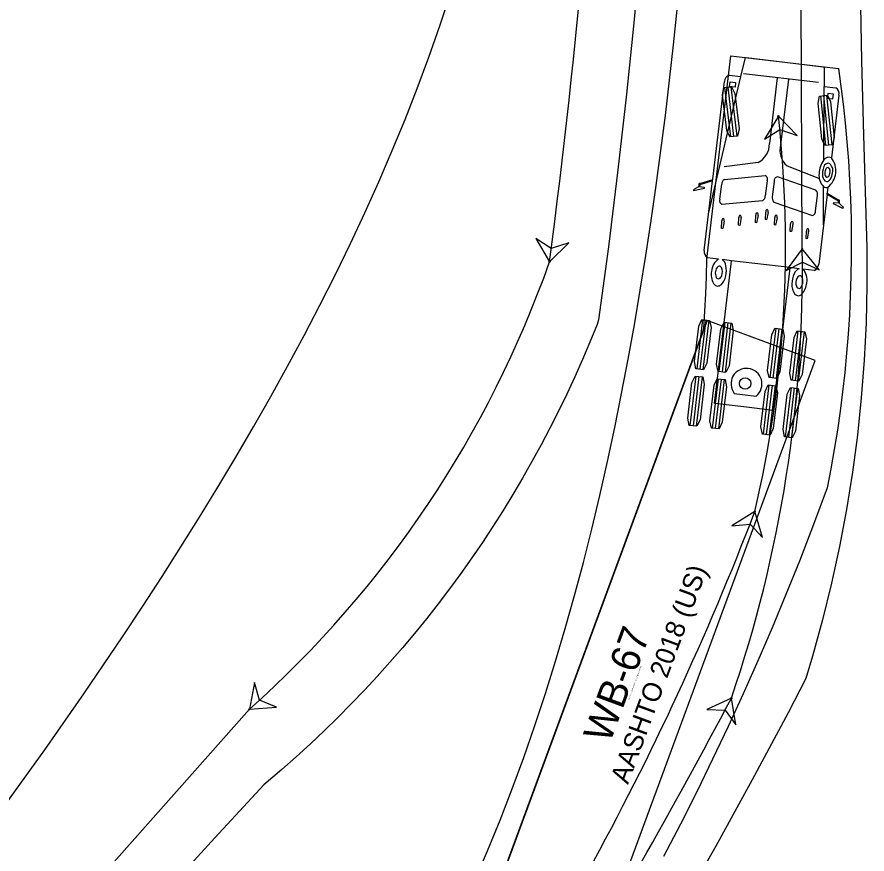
# Model space of a CAD drawing. Extents: x 973688 to 979179, y 703586 to 707602.
# Drawn here: x 976668.5 to 976731.2, y 705666.2 to 705727.9 of the extents above; entities that cross this region are included whole.
import ezdxf

# ---------------------------------------------------------------- set-up
doc = ezdxf.new("R2010")
doc.units = 0
doc.layers.add('EB Left', color=7, linetype='Continuous')
doc.layers.add('SB Right', color=7, linetype='Continuous')

msp = doc.modelspace()

# ---------------------------------------------------------------- linework, layer by layer
at = {"layer": 'EB Left'}
msp.add_line((976726.438, 705710.847), (976726.065, 705823.129), dxfattribs=at)
for points in [[(976702.259, 705664.192), (976703.224, 705666.439), (976704.151, 705668.711), (976705.041, 705671.008), (976705.895, 705673.329), (976706.714, 705675.674), (976707.497, 705678.04), (976708.247, 705680.428), (976708.963, 705682.837), (976709.647, 705685.264), (976710.299, 705687.71), (976710.92, 705690.173), (976711.511, 705692.651), (976712.074, 705695.145), (976712.609, 705697.652), (976713.118, 705700.172), (976713.6, 705702.704), (976714.058, 705705.246), (976714.492, 705707.799), (976714.904, 705710.361), (976715.294, 705712.931), (976715.663, 705715.51), (976716.343, 705720.687), (976716.95, 705725.889), (976717.493, 705731.11)], [(976730.706, 705730.152), (976730.816, 705724.697), (976730.954, 705719.214), (976731.211, 705710.924), (976731.221, 705708.153), (976731.156, 705705.384), (976731.016, 705702.619), (976730.8, 705699.858), (976730.509, 705697.104), (976730.144, 705694.357), (976729.704, 705691.62), (976729.188, 705688.894), (976728.599, 705686.181), (976727.935, 705683.484), (976727.198, 705680.805), (976726.699, 705679.141), (976725.396, 705676.628), (976722.75, 705671.666), (976720.066, 705666.787), (976717.348, 705661.995)], [(976726.438, 705710.847), (976725.249, 705709.239), (976726.456, 705709.847), (976727.683, 705709.282), (976726.438, 705710.847)], [(976721.216, 705677.7), (976719.398, 705676.865), (976720.749, 705676.815), (976721.552, 705675.728), (976721.216, 705677.7)]]:
    msp.add_lwpolyline(points, dxfattribs=at)
for points in [[(976726.438, 705710.847), (976725.249, 705709.239), (976726.456, 705709.847), (976727.683, 705709.282)], [(976721.216, 705677.7), (976719.398, 705676.865), (976720.749, 705676.815), (976721.552, 705675.728)]]:
    msp.add_lwpolyline(points, close=True, dxfattribs=at)
for centre in [(976726.438, 705710.847), (976721.216, 705677.7)]:
    msp.add_circle(centre, 0.0417, dxfattribs=at)
for centre, radius, start, end in [((976629.35, 705709.159), 97.103, 341.09639, 0.99621), ((976347.09, 705875.165), 423.04, 324.68102, 332.17475)]:
    msp.add_arc(centre, radius, start, end, dxfattribs=at)
at = {"layer": 'SB Right'}
for p, q in [((976727.632, 705723.1), (976722.108, 705723.759)), ((976719.566, 705713.629), (976721.919, 705723.555)), ((976721.074, 705722.814), (976721.117, 705723.167)), ((976721.117, 705723.167), (976721.526, 705723.118)), ((976721.526, 705723.118), (976721.484, 705722.765)), ((976724.6, 705723.462), (976724.02, 705718.605)), ((976725.428, 705723.363), (976724.848, 705718.506)), ((976720.72, 705722.737), (976721.156, 705719.096)), ((976720.947, 705722.764), (976721.384, 705719.124)), ((976721.484, 705722.765), (976721.074, 705722.814)), ((976721.175, 705722.792), (976721.611, 705719.151)), ((976728.029, 705717.395), (976728.055, 705722.822)), ((976727.783, 705722.115), (976728.16, 705718.468)), ((976728.011, 705722.139), (976728.388, 705718.491)), ((976728.239, 705722.162), (976728.616, 705718.515)), ((976728.334, 705722.306), (976728.292, 705721.953)), ((976728.292, 705721.953), (976728.702, 705721.904)), ((976728.744, 705722.257), (976728.334, 705722.306)), ((976728.702, 705721.904), (976728.744, 705722.257)), ((976723.197, 705717.213), (976720.672, 705716.877)), ((976725.321, 705716.959), (976727.708, 705716.034)), ((976720.707, 705715.962), (976723.699, 705716.255)), ((976719.833, 705715.863), (976719.845, 705715.962)), ((976720.366, 705714.492), (976720.5, 705715.614)), ((976723.852, 705715.863), (976723.718, 705714.741)), ((976724.367, 705715.802), (976724.233, 705714.679)), ((976727.446, 705715.158), (976724.607, 705716.146)), ((976718.84, 705715.455), (976718.816, 705715.441)), ((976718.868, 705715.45), (976718.84, 705715.455)), ((976728.006, 705712.622), (976728.02, 705715.428)), ((976728.273, 705714.856), (976728.285, 705714.955)), ((976723.51, 705714.393), (976720.518, 705714.1)), ((976724.353, 705714.292), (976727.192, 705713.304)), ((976727.432, 705713.648), (976727.566, 705714.771)), ((976729.113, 705714.228), (976729.141, 705714.226)), ((976729.141, 705714.226), (976729.162, 705714.206)), ((976721.739, 705712.584), (976721.767, 705713.16)), ((976721.934, 705713.14), (976721.828, 705712.574)), ((976722.987, 705712.772), (976723.014, 705713.322)), ((976723.181, 705713.302), (976723.077, 705712.761)), ((976723.725, 705712.995), (976723.752, 705713.545)), ((976723.919, 705713.525), (976723.815, 705712.984)), ((976724.39, 705712.605), (976724.416, 705713.155)), ((976724.583, 705713.135), (976724.479, 705712.594)), ((976720.484, 705712.346), (976720.51, 705712.896)), ((976720.678, 705712.876), (976720.573, 705712.335)), ((976721.828, 705712.574), (976721.739, 705712.584)), ((976723.077, 705712.761), (976722.987, 705712.772)), ((976723.815, 705712.984), (976723.725, 705712.995)), ((976724.479, 705712.594), (976724.39, 705712.605)), ((976725.559, 705712.128), (976725.586, 705712.679)), ((976725.753, 705712.659), (976725.649, 705712.118)), ((976720.573, 705712.335), (976720.484, 705712.346)), ((976725.649, 705712.118), (976725.559, 705712.128)), ((976726.723, 705711.601), (976726.749, 705712.151)), ((976726.916, 705712.132), (976726.812, 705711.59)), ((976726.812, 705711.59), (976726.723, 705711.601)), ((976725.529, 705709.454), (976721.229, 705709.967)), ((976719.093, 705705.623), (976718.659, 705701.982)), ((976719.321, 705705.596), (976718.886, 705701.955)), ((976719.548, 705705.569), (976719.114, 705701.928)), ((976720.732, 705705.428), (976720.297, 705701.787)), ((976720.959, 705705.4), (976720.525, 705701.76)), ((976721.187, 705705.373), (976720.752, 705701.732)), ((976724.488, 705704.979), (976724.054, 705701.338)), ((976724.716, 705704.952), (976724.281, 705701.311)), ((976724.943, 705704.925), (976724.509, 705701.284)), ((976726.127, 705704.784), (976725.692, 705701.143)), ((976726.354, 705704.757), (976725.92, 705701.116)), ((976726.582, 705704.729), (976726.147, 705701.089)), ((976718.596, 705701.453), (976718.161, 705697.812)), ((976718.823, 705701.426), (976718.389, 705697.785)), ((976719.051, 705701.398), (976718.616, 705697.758)), ((976720.234, 705701.257), (976719.8, 705697.616)), ((976720.462, 705701.23), (976720.027, 705697.589)), ((976720.689, 705701.203), (976720.255, 705697.562)), ((976723.991, 705700.809), (976723.556, 705697.168)), ((976724.218, 705700.782), (976723.784, 705697.141)), ((976724.446, 705700.755), (976724.011, 705697.114)), ((976725.629, 705700.613), (976725.195, 705696.972)), ((976725.857, 705700.586), (976725.422, 705696.945)), ((976726.084, 705700.559), (976725.65, 705696.918)), ((976721.432, 705700.176), (976723.037, 705699.984)), ((976685.668, 705676.879), (976635.767, 705620.712))]:
    msp.add_line(p, q, dxfattribs=at)
for points in [[(976714.521, 705733.032), (976714.039, 705727.751), (976713.479, 705722.257), (976712.849, 705716.671), (976712.145, 705710.995), (976711.417, 705705.6), (976711.306, 705705.266), (976710.779, 705703.966), (976710.23, 705702.675), (976709.661, 705701.394), (976709.07, 705700.124), (976708.459, 705698.863), (976707.828, 705697.613), (976707.176, 705696.375), (976706.504, 705695.148), (976705.813, 705693.932), (976705.101, 705692.729), (976704.371, 705691.538), (976703.621, 705690.359), (976702.851, 705689.193), (976702.063, 705688.04), (976701.256, 705686.901), (976700.43, 705685.774), (976699.586, 705684.662), (976698.724, 705683.563), (976697.843, 705682.478), (976696.944, 705681.408), (976696.028, 705680.351), (976695.093, 705679.31), (976694.14, 705678.283), (976693.17, 705677.271), (976692.182, 705676.273), (976691.176, 705675.292), (976690.153, 705674.325), (976689.112, 705673.374), (976688.053, 705672.439), (976686.731, 705671.31), (976683.104, 705667.39), (976681.323, 705665.437)], [(976667.634, 705669.825), (976670.553, 705673.881), (976673.451, 705678.03), (976676.347, 705682.299), (976677.789, 705684.477), (976679.21, 705686.663), (976680.609, 705688.856), (976681.986, 705691.058), (976683.339, 705693.268), (976684.665, 705695.486), (976685.965, 705697.712), (976687.237, 705699.945), (976688.478, 705702.187), (976689.688, 705704.437), (976690.864, 705706.694), (976692.006, 705708.958), (976693.112, 705711.23), (976694.18, 705713.508), (976695.208, 705715.792), (976696.196, 705718.082), (976697.14, 705720.377), (976698.041, 705722.677), (976698.896, 705724.982), (976699.705, 705727.29), (976700.467, 705729.602)], [(976704.605, 705665.378), (976719.091, 705704.657), (976719.179, 705704.962), (976719.266, 705706.237), (976719.333, 705707.514), (976719.379, 705708.791), (976719.405, 705710.07), (976721.184, 705725.079), (976729.128, 705724.131), (976729.467, 705721.518), (976729.617, 705720.125), (976729.745, 705718.727), (976729.852, 705717.322), (976729.938, 705715.912), (976730.002, 705714.496), (976730.044, 705713.073), (976730.064, 705711.67), (976730.061, 705710.248), (976730.037, 705708.825), (976729.99, 705707.4), (976729.921, 705705.977), (976729.83, 705704.555), (976729.716, 705703.134), (976729.58, 705701.715), (976729.422, 705700.297), (976729.241, 705698.879), (976729.037, 705697.462), (976728.811, 705696.044), (976728.561, 705694.626), (976728.278, 705693.211), (976727.273, 705690.506), (976726.233, 705687.816), (976725.243, 705685.35), (976724.223, 705682.895), (976723.171, 705680.452), (976722.089, 705678.02), (976720.976, 705675.6), (976719.832, 705673.191), (976718.658, 705670.793), (976717.451, 705668.407), (976716.214, 705666.033)], [(976721.06, 705723.657), (976721.911, 705723.556), (976721.92, 705723.557), (976722.25, 705724.951), (976722.313, 705724.944), (976725.156, 705724.605), (976727.999, 705724.266), (976728.062, 705724.258), (976728.055, 705722.824), (976728.064, 705722.821), (976728.914, 705722.72)], [(976718.887, 705715.655), (976719.835, 705715.959), (976719.846, 705715.97), (976720.705, 705723.176)], [(976729.146, 705722.168), (976728.595, 705717.557)], [(976724.682, 705720.633), (976723.648, 705718.921), (976724.793, 705719.639), (976726.068, 705719.191), (976724.682, 705720.633)], [(976719.219, 705710.723), (976719.833, 705715.863), (976718.895, 705715.567), (976718.895, 705715.567), (976718.879, 705715.532), (976718.878, 705715.531), (976718.878, 705715.53), (976718.868, 705715.451), (976718.869, 705715.45), (976719.213, 705715.393), (976719.201, 705715.291), (976718.456, 705715.121), (976718.454, 705715.121), (976718.468, 705715.239), (976718.471, 705715.241), (976718.814, 705715.44), (976718.816, 705715.442), (976718.827, 705715.528)], [(976728.336, 705715.386), (976728.286, 705714.963), (976728.293, 705714.95), (976729.143, 705714.431)], [(976729.171, 705714.293), (976729.162, 705714.207), (976729.163, 705714.205), (976729.45, 705713.931), (976729.452, 705713.929), (976729.438, 705713.811), (976729.436, 705713.81), (976728.753, 705714.151), (976728.765, 705714.253), (976729.112, 705714.228), (976729.113, 705714.228), (976729.122, 705714.308), (976729.122, 705714.309), (976729.122, 705714.309), (976729.115, 705714.347), (976729.114, 705714.347), (976728.273, 705714.856), (976727.66, 705709.716)], [(976707.797, 705709.874), (976709.213, 705711.287), (976707.929, 705710.866), (976706.799, 705711.608), (976707.797, 705709.874)], [(976720.267, 705710.082), (976719.428, 705710.182)], [(976726.21, 705709.373), (976725.529, 705709.454), (976725.5, 705709.218), (976724.273, 705698.929), (976722.123, 705699.185), (976719.973, 705699.442), (976721.201, 705709.731), (976721.228, 705709.967), (976720.547, 705710.049)], [(976727.329, 705709.239), (976726.49, 705709.339)], [(976709.062, 705652.962), (976709.083, 705652.955), (976709.107, 705653.021), (976711.069, 705658.338), (976727.397, 705702.615), (976723.409, 705704.085), (976719.422, 705705.556), (976703.094, 705661.279), (976701.133, 705655.962), (976701.109, 705655.895), (976701.129, 705655.888)], [(976722.947, 705691.462), (976721.243, 705690.415), (976722.59, 705690.528), (976723.517, 705689.545), (976722.947, 705691.462)], [(976685.668, 705676.879), (976687.662, 705677.028), (976686.413, 705677.545), (976686.04, 705678.844), (976685.668, 705676.879)]]:
    msp.add_lwpolyline(points, dxfattribs=at)
for points in [[(976720.663, 705722.73), (976721.231, 705722.798), (976721.463, 705722.309), (976721.778, 705719.688), (976721.668, 705719.158), (976721.1, 705719.09), (976720.868, 705719.579), (976720.553, 705722.2)], [(976727.727, 705722.109), (976728.296, 705722.168), (976728.52, 705721.675), (976728.791, 705719.049), (976728.673, 705718.521), (976728.104, 705718.462), (976727.88, 705718.955), (976727.608, 705721.581)], [(976724.682, 705720.633), (976723.648, 705718.921), (976724.793, 705719.639), (976726.068, 705719.191)], [(976707.797, 705709.874), (976709.213, 705711.287), (976707.929, 705710.866), (976706.799, 705711.608)], [(976719.037, 705705.63), (976719.605, 705705.562), (976719.715, 705705.032), (976719.402, 705702.41), (976719.17, 705701.921), (976718.602, 705701.989), (976718.492, 705702.519), (976718.805, 705705.141)], [(976720.675, 705705.434), (976721.243, 705705.367), (976721.354, 705704.836), (976721.041, 705702.215), (976720.809, 705701.726), (976720.241, 705701.793), (976720.13, 705702.324), (976720.443, 705704.945)], [(976724.432, 705704.986), (976725, 705704.918), (976725.11, 705704.388), (976724.797, 705701.767), (976724.565, 705701.277), (976723.997, 705701.345), (976723.887, 705701.875), (976724.2, 705704.497)], [(976726.07, 705704.79), (976726.638, 705704.723), (976726.749, 705704.193), (976726.436, 705701.571), (976726.204, 705701.082), (976725.636, 705701.15), (976725.526, 705701.68), (976725.838, 705704.301)], [(976718.539, 705701.459), (976719.107, 705701.392), (976719.217, 705700.861), (976718.905, 705698.24), (976718.673, 705697.751), (976718.105, 705697.819), (976717.994, 705698.349), (976718.307, 705700.97)], [(976720.178, 705701.264), (976720.746, 705701.196), (976720.856, 705700.666), (976720.543, 705698.045), (976720.311, 705697.555), (976719.743, 705697.623), (976719.633, 705698.153), (976719.946, 705700.775)], [(976723.934, 705700.816), (976724.502, 705700.748), (976724.612, 705700.218), (976724.3, 705697.596), (976724.068, 705697.107), (976723.5, 705697.175), (976723.389, 705697.705), (976723.702, 705700.326)], [(976725.573, 705700.62), (976726.141, 705700.552), (976726.251, 705700.022), (976725.938, 705697.401), (976725.706, 705696.911), (976725.138, 705696.979), (976725.028, 705697.509), (976725.341, 705700.131)], [(976722.947, 705691.462), (976721.243, 705690.415), (976722.59, 705690.528), (976723.517, 705689.545)], [(976685.668, 705676.879), (976687.662, 705677.028), (976686.413, 705677.545), (976686.04, 705678.844)]]:
    msp.add_lwpolyline(points, close=True, dxfattribs=at)
for centre, radius in [((976724.682, 705720.633), 0.0417), ((976707.797, 705709.874), 0.0417), ((976707.797, 705709.874), 0.0417), ((976722.237, 705700.906), 0.424), ((976722.947, 705691.462), 0.0417), ((976722.947, 705691.462), 0.0417), ((976685.668, 705676.879), 0.0417), ((976685.668, 705676.879), 0.0417)]:
    msp.add_circle(centre, radius, dxfattribs=at)
for centre, radius, start, end in [((976200.719, 705777.287), 511.539, 352.42731, 357.81534), ((976721.191, 705723.189), 0.486, 105.65763, 181.60874), ((976728.677, 705722.296), 0.486, 344.7806, 60.7317), ((976639.025, 705711.092), 86.187, 346.83516, 6.35624), ((976722.504, 705718.562), 1.517, 297.18721, 1.61462), ((976726.312, 705718.107), 1.517, 164.77471, 229.20213), ((976728.389, 705717.169), 0.425, 61.2576, 147.79396), ((976727.401, 705716.6), 1.53, 307.6874, 38.69645), ((976729.392, 705716.373), 1.704, 143.11535, 179.02342), ((976729.118, 705716.386), 1.189, 154.32587, 190.21519), ((976728.397, 705716.799), 0.366, 91.24701, 163.72799), ((976728.345, 705716.678), 0.158, 88.16589, 149.67864), ((976728.274, 705716.625), 0.223, 0.42957, 70.03206), ((976728.07, 705716.617), 0.634, 343.77853, 59.78024), ((976723.581, 705715.983), 0.296, 336.17823, 66.47591), ((976728.813, 705716.242), 1.136, 171.89921, 225.70177), ((976728.386, 705716.214), 0.44, 184.98891, 248.80176), ((976728.373, 705716.373), 0.263, 172.12958, 246.0315), ((976728.687, 705716.438), 0.575, 146.26978, 182.84011), ((976728.263, 705716.303), 0.17, 270.86373, 324.92807), ((976727.914, 705716.536), 0.589, 325.95019, 8.93291), ((976727.654, 705716.54), 1.03, 326.01832, 354.40483), ((976718.92, 705715.582), 0.108, 164.03584, 210.21834), ((976718.869, 705715.606), 0.0522, 69.45745, 174.31207), ((976720.886, 705715.619), 0.387, 117.52752, 180.75948), ((976724.658, 705715.855), 0.296, 99.91343, 190.2111), ((976728.232, 705716.12), 0.317, 269.04486, 330.63726), ((976727.192, 705714.867), 0.387, 345.62985, 48.86182), ((976728.216, 705715.714), 0.347, 235.52188, 290.33246), ((976720.682, 705714.39), 0.332, 162.11607, 240.53807), ((976723.331, 705714.736), 0.387, 297.52997, 0.75703), ((976724.607, 705714.583), 0.387, 165.6323, 228.85937), ((976729.149, 705714.38), 0.0522, 352.07726, 96.93188), ((976729.094, 705714.368), 0.108, 316.171, 2.35349), ((976723.904, 705713.583), 0.157, 106.74065, 193.85031), ((976723.779, 705713.597), 0.157, 332.53902, 59.64869), ((976727.101, 705713.624), 0.332, 285.85126, 4.27326), ((976720.663, 705712.934), 0.157, 106.74065, 193.85031), ((976720.504, 705712.939), 0.184, 340.14785, 52.03986), ((976721.917, 705713.172), 0.157, 106.74065, 193.85031), ((976721.759, 705713.177), 0.184, 340.14785, 52.03986), ((976723.166, 705713.36), 0.157, 106.74065, 193.85031), ((976723.007, 705713.365), 0.184, 340.14785, 52.03986), ((976724.599, 705713.175), 0.184, 114.34947, 186.24149), ((976724.444, 705713.207), 0.157, 332.53902, 59.64869), ((976725.769, 705712.699), 0.184, 114.34947, 186.24149), ((976725.614, 705712.731), 0.157, 332.53902, 59.64869), ((976726.932, 705712.172), 0.184, 114.34947, 186.24149), ((976726.777, 705712.204), 0.157, 332.53902, 59.64869), ((976719.834, 705710.65), 0.619, 173.19264, 229.03435), ((976720.883, 705709.127), 1.136, 122.8246, 177.6159), ((976720.094, 705709.478), 0.729, 9.00315, 51.51715), ((976632.356, 705736.553), 80.02, 311.7769, 340.52466), ((976720.564, 705709.126), 0.522, 128.20003, 175.36416), ((976720.33, 705709.394), 0.169, 21.62899, 121.74771), ((976719.822, 705709.151), 0.732, 338.36849, 24.60293), ((976719.12, 705709.238), 1.73, 347.02131, 11.81981), ((976726.517, 705708.712), 0.729, 114.87218, 157.38618), ((976725.667, 705708.557), 1.136, 348.77344, 43.56473), ((976727.045, 705709.789), 0.619, 297.35498, 353.19669), ((976721.147, 705708.956), 1.416, 171.12282, 208.19067), ((976720.694, 705709.032), 0.664, 168.0985, 206.32021), ((976720.256, 705708.806), 0.172, 203.49627, 290.64686), ((976720.15, 705708.966), 0.362, 297.49123, 346.53221), ((976719.686, 705709.037), 1.136, 308.95863, 350.47938), ((976727.407, 705708.249), 1.73, 154.56952, 179.36803), ((976726.704, 705708.33), 0.732, 141.78641, 188.02084), ((976726.267, 705708.685), 0.169, 44.64162, 144.76034), ((976725.976, 705708.481), 0.522, 351.02518, 38.1893), ((976720.208, 705708.442), 0.346, 206.58737, 303.60042), ((976726.81, 705708.187), 1.136, 175.90996, 217.4307), ((976726.342, 705708.227), 0.362, 179.85712, 228.89811), ((976725.828, 705708.419), 0.664, 320.06912, 358.29084), ((976725.37, 705708.452), 1.416, 318.19866, 355.26652), ((976726.161, 705707.731), 0.346, 222.78891, 319.80197), ((976726.201, 705708.096), 0.172, 235.74247, 322.89306), ((976722.33, 705700.883), 1.143, 308.19467, 218.19467), ((976525.035, 705767.141), 211.887, 331.14948, 339.07382)]:
    msp.add_arc(centre, radius, start, end, dxfattribs=at)
for centre, major_axis, start_param, end_param in [((976718.857, 705715.592), (0.0093, 0.0777), 2.615166, 3.884468), ((976718.857, 705715.592), (-0.0093, -0.0777), 1.301202, 2.571945), ((976729.158, 705714.363), (0.0093, 0.0777), 0.569648, 1.840391), ((976729.158, 705714.363), (0.0093, 0.0777), 2.398717, 3.668019)]:
    msp.add_ellipse(centre, major_axis=major_axis, ratio=0.544872, start_param=start_param, end_param=end_param, dxfattribs=at)

# ---------------------------------------------------------------- texts
for s, height, p in [('AASHTO 2018 (US)', 1.41667, (976713.589, 705671.293)), ('WB-67', 2.125, (976712.243, 705674.297)), ('(c) 2020 Transoft Solutions, Inc. All rights reserved.', 0.085, (976713.678, 705677.574))]:
    msp.add_text(s, height=height, rotation=69.75705, dxfattribs=at).set_placement(p)

doc.saveas('drawing.dxf')
